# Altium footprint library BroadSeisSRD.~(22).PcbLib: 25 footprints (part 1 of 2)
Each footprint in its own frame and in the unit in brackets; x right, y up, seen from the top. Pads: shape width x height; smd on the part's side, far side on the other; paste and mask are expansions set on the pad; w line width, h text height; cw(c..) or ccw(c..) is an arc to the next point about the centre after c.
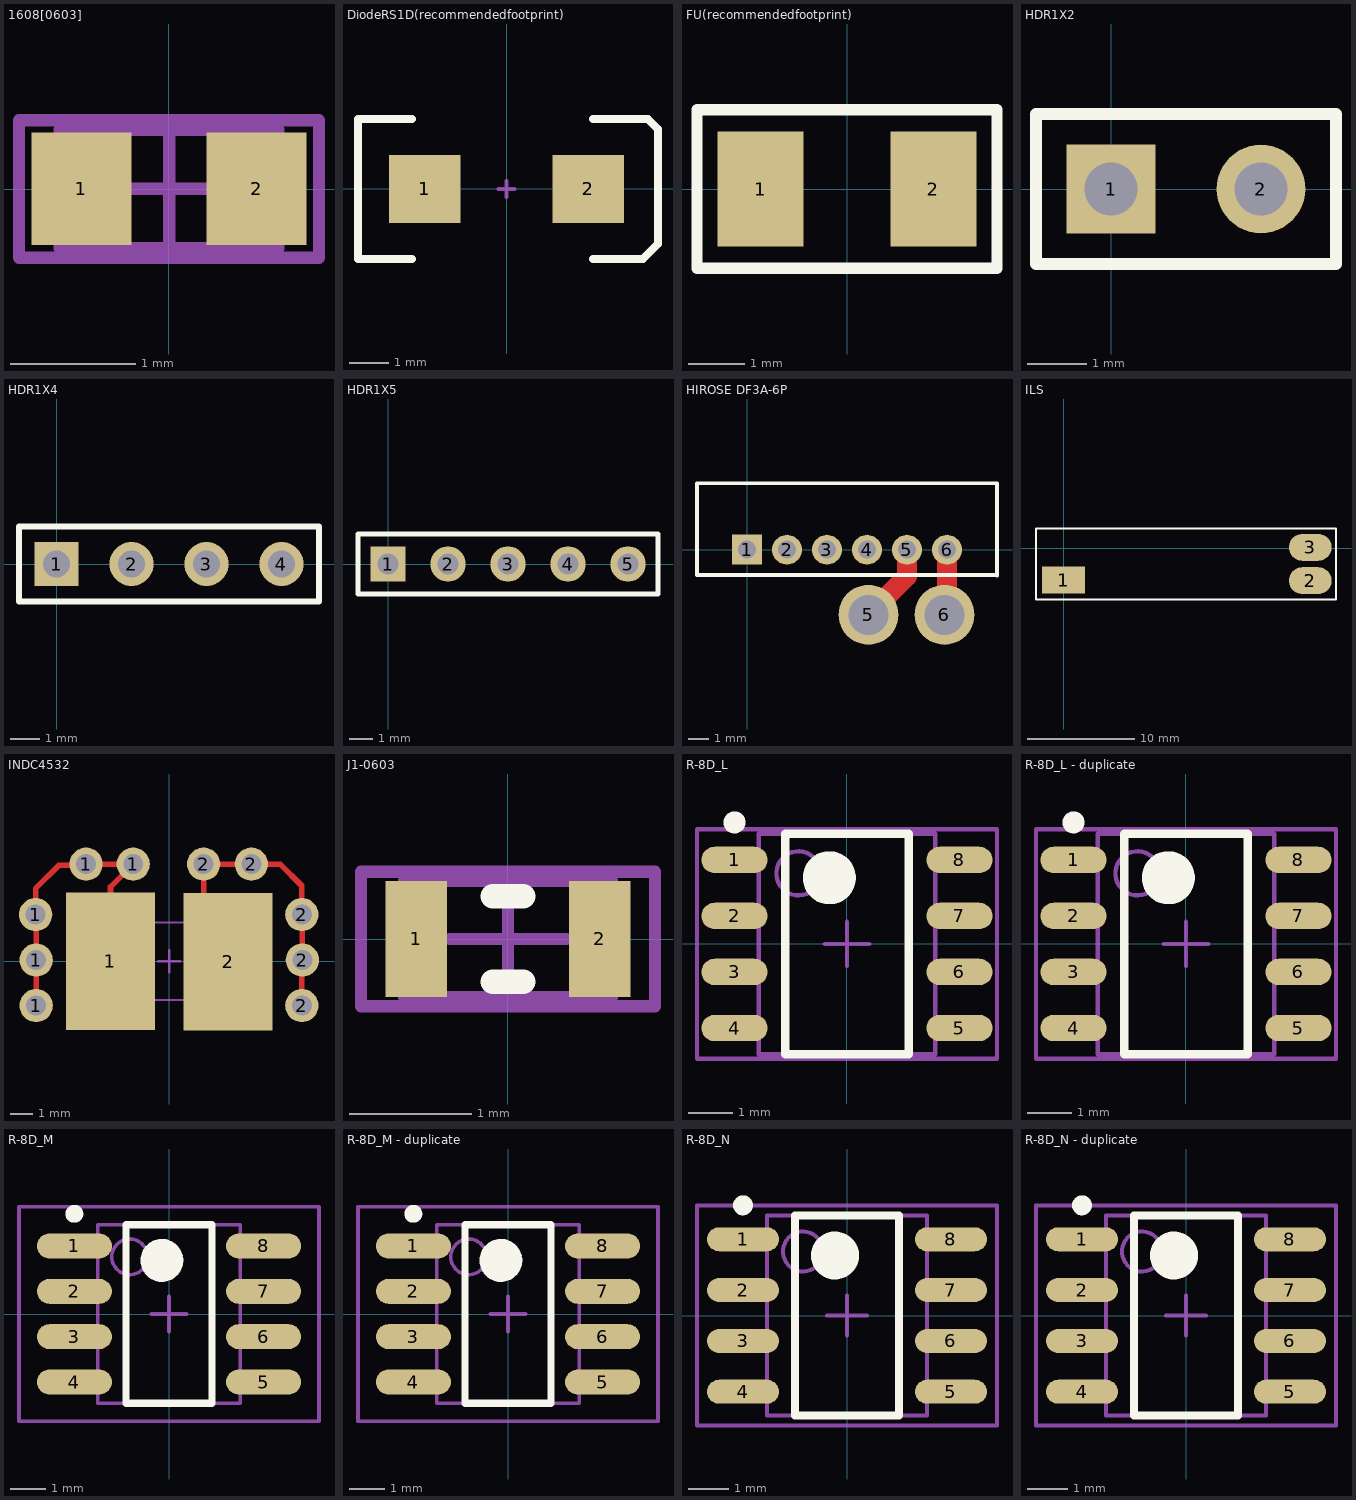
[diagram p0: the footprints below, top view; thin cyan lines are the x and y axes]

## 1608[0603] [mm] "Chip Capacitor, Body 1.6x0.8mm, IPC High Density"
height 1.3
pads (2):
  rect 0.8x0.9 smd: 1(-0.7,0) 2(0.7,0)
Mechanical 13:
  lines w0.1: -0.875,-0.475 0.875,-0.475 0.875,0.475 -0.875,0.475 -0.875,-0.475
Mechanical 15:
  lines w0.1: -0.475,0 0.475,0 ; 0,-0.475 0,0.475 ; -1.2,-0.55 1.2,-0.55 1.2,0.55 -1.2,0.55 -1.2,-0.55
3D body: height 1.3, standoff 0, extent -0.875,-0.475 0.875,0.475

## DiodeRS1D(recommendedfootprint) [mm] "DO-214-AB/SMC; 2 C-Bend Leads; Body 7.9 x 5.9 mm, inc. leads (LxW)"
height 2.65
pads (2):
  rect 1.8x1.7 smd: 1(-2.05,0) 2(2.05,0)
Top Overlay:
  lines w0.2: -2.375,-1.75 -3.725,-1.75 -3.725,1.75 -2.375,1.75 ; 2.175,-1.75 3.425,-1.75 3.8,-1.375 3.8,1.499 3.552,1.75 2.175,1.75
Mechanical 1:
  lines w0.1: -0.2,0 0.2,0 ; 0,-0.2 0,0.2

## FU(recommendedfootprint) [mm] "Thru-Hole; 2 Leads"
pads (2):
  rect 1.52x2.03 smd: 1(-1.525,0) 2(1.525,0)
Top Overlay:
  lines w0.2: -2.65,-1.4 2.65,-1.4 2.65,1.4 -2.65,1.4 -2.65,-1.4

## HDR1X2 [mm] "Connector; Header; 2 Position"
pads (2):
  rect 1.5x1.5 hole 0.9: 1(0,0)
  round 1.5 hole 0.9: 2(2.54,0)
Top Overlay:
  lines w0.2: -1.27,-1.27 3.81,-1.27 3.81,1.27 -1.27,1.27 -1.27,-1.27

## HDR1X4 [mm] "Connector; Header; 4 Position"
pads (4):
  rect 1.5x1.5 hole 0.9: 1(0,0)
  round 1.5 hole 0.9: 2(2.54,0) 3(5.08,0) 4(7.62,0)
Top Overlay:
  lines w0.2: -1.27,-1.27 -1.27,1.27 8.89,1.27 8.89,-1.27 -1.27,-1.27

## HDR1X5 [mm] "Connector; Header; 5 Position"
pads (5):
  rect 1.5x1.5 hole 0.9: 1(0,0)
  round 1.5 hole 0.9: 2(2.54,0) 3(5.08,0) 4(7.62,0) 5(10.16,0)
Top Overlay:
  lines w0.2: -1.27,-1.27 -1.27,1.27 11.43,1.27 11.43,-1.27 -1.27,-1.27

## HIROSE DF3A-6P [mm] "Connector; Header; 6 Position"
pads (8):
  rect 1.5x1.5 hole 0.9: 1(0,0)
  round 1.5 hole 0.9: 2(2,0) 3(4,0) 4(6,0) 5(8,0) 6(10,0)
  round 3 hole 2: 5(6.075,-3.25) 6(9.875,-3.25)
Top Layer:
  lines w0.254: 9.875,-3.25 10,-2.75
  lines w1: 6.075,-3.25 8,-1.325 8,0 ; 10,-2.75 10,0
Top Overlay:
  lines w0.2: 12.5,-1.29 12.5,3.325 -2.5,3.325 -2.5,-1.27 12.5,-1.27

## ILS [mm]
pads (3):
  rect 4x2.5 smd: 1(0,-2.95)
  oval 4x2.5 smd: 2(23,-3) 3(23,0.1)
Top Overlay:
  lines w0.2: -2.575,-4.775 25.4,-4.775 25.4,1.85 -2.575,1.85 -2.575,-4.775

## INDC4532 [mm] "Chip Inductor, Body 4.5x3.2mm, IPC High Density"
height 0.55
pads (12):
  round 1.5 hole 0.9: 1(-6.025,2.1) 1(-6,-2) 1(-6,0.05) 1(-3.75,4.375) 1(-1.625,4.375) 2(1.55,4.375) 2(3.7,4.375) 2(5.975,-2) 2(5.975,2.1) 2(6,0.05)
  rect 4x6.2 smd: 1(-2.65,0) 2(2.65,-0.025)
Top Layer:
  lines w0.254: -6,-2 -6,0.05 ; -5.975,0.075 -6,0.05 ; -5.825,2.075 -6.025,2.1 ; -3.725,4.15 -3.75,4.375 ; -1.625,1.025 -2.65,0 -2.65,3.35 -1.625,4.375 -3.75,4.375 ; 2.65,1.2 2.65,-0.025 1.55,1.075 1.55,4.375 3.7,4.375 ; 3.725,4.2 3.7,4.375 ; 3.75,4.425 3.7,4.375 ; 5.95,-1.975 5.975,-2 5.975,0.025 ; -6.025,2.1 -6,2.075 -6,0.05 ; -6.025,2.1 -6.025,3.275 -4.975,4.325 -3.8,4.325 -3.75,4.375 ; 3.7,4.375 5,4.375 5.975,3.4 5.975,2.1 ; 5.975,0.025 6,0.05 ; 5.975,0.025 6,0.05 ; 5.975,2.1 6,2.075 ; 5.975,2.1 6,2.075 ; 6,0.05 6,2.075
Mechanical 13:
  lines w0.1: -2.4,-1.7 -2.4,1.7 ; 2.4,-1.7 2.4,1.7
Mechanical 15:
  lines w0.1: -0.5,0 0.5,0 ; 0,-0.5 0,0.5 ; -2.7,-1.75 2.7,-1.75 2.7,1.75 -2.7,1.75 -2.7,-1.75

## J1-0603 [mm] "Chip Resistor, Body 1.6x0.8mm, IPC High Density"
height 0.9
pads (2):
  rect 0.5x0.95 smd: 1(-0.75,0) 2(0.75,0)
Top Overlay:
  lines w0.2: -0.125,-0.35 0.125,-0.35 ; -0.125,0.35 0.125,0.35
Mechanical 13:
  lines w0.1: -0.85,-0.475 0.85,-0.475 0.85,0.475 -0.85,0.475 -0.85,-0.475
Mechanical 15:
  lines w0.1: -0.475,0 0.475,0 ; 0,-0.475 0,0.475 ; -1.2,-0.55 1.2,-0.55 1.2,0.55 -1.2,0.55 -1.2,-0.55
3D body: height 0.9, standoff 0, extent -0.85,-0.475 0.85,0.475

## R-8D_L [mm] "SOIC, 8-Leads, Body 4.9x3.9mm, Pitch 1.27mm, IPC High Density"
height 2.59
pads (8):
  oval 1.5x0.6 smd: 1(-2.55,1.905) 2(-2.55,0.635) 3(-2.55,-0.635) 4(-2.55,-1.905) 5(2.55,-1.905) 6(2.55,-0.635) 7(2.55,0.635) 8(2.55,1.905)
Top Overlay:
  circle w0.6: c-0.4,1.5 r0.3
  circle w0.25: c-2.55,2.755 r0.125
  lines w0.2: -1.4,-2.5 1.4,-2.5 1.4,2.5 -1.4,2.5 -1.4,-2.5
Mechanical 13:
  circle w0.1: c-1.1,1.6 r0.5
  lines w0.1: -2,-2.5 2,-2.5 2,2.5 -2,2.5 -2,-2.5
Mechanical 15:
  lines w0.1: -0.5,0 0.5,0 ; 0,-0.5 0,0.5 ; -3.4,-2.6 3.4,-2.6 3.4,2.6 -3.4,2.6 -3.4,-2.6
3D body: height 2.59, standoff 0, extent -2,-2.5 2,2.5

## R-8D_L - duplicate [mm] "SOIC, 8-Leads, Body 4.9x3.9mm, Pitch 1.27mm, IPC High Density"
height 2.59
pads (8):
  oval 1.5x0.6 smd: 1(-2.55,1.905) 2(-2.55,0.635) 3(-2.55,-0.635) 4(-2.55,-1.905) 5(2.55,-1.905) 6(2.55,-0.635) 7(2.55,0.635) 8(2.55,1.905)
Top Overlay:
  circle w0.6: c-0.4,1.5 r0.3
  circle w0.25: c-2.55,2.755 r0.125
  lines w0.2: -1.4,-2.5 1.4,-2.5 1.4,2.5 -1.4,2.5 -1.4,-2.5
Mechanical 13:
  circle w0.1: c-1.1,1.6 r0.5
  lines w0.1: -2,-2.5 2,-2.5 2,2.5 -2,2.5 -2,-2.5
Mechanical 15:
  lines w0.1: -0.5,0 0.5,0 ; 0,-0.5 0,0.5 ; -3.4,-2.6 3.4,-2.6 3.4,2.6 -3.4,2.6 -3.4,-2.6
3D body: height 2.59, standoff 0, extent -2,-2.5 2,2.5

## R-8D_M [mm] "SOIC, 8-Leads, Body 4.9x3.9mm, Pitch 1.27mm, IPC Low Density"
height 2.59
pads (8):
  oval 2.1x0.7 smd: 1(-2.65,1.905) 2(-2.65,0.635) 3(-2.65,-0.635) 4(-2.65,-1.905) 5(2.65,-1.905) 6(2.65,-0.635) 7(2.65,0.635) 8(2.65,1.905)
Top Overlay:
  circle w0.25: c-2.65,2.805 r0.125
  circle w0.6: c-0.2,1.5 r0.3
  lines w0.2: -1.2,-2.5 -1.2,2.5 1.2,2.5 1.2,-2.5 -1.2,-2.5
Mechanical 13:
  circle w0.1: c-1.1,1.6 r0.5
  lines w0.1: -2,-2.5 -2,2.5 2,2.5 2,-2.5 -2,-2.5
Mechanical 15:
  lines w0.1: -0.5,0 0.5,0 ; 0,-0.5 0,0.5 ; -4.2,-3 -4.2,3 4.2,3 4.2,-3 -4.2,-3
3D body: height 2.59, standoff 0, extent -2,-2.5 2,2.5

## R-8D_M - duplicate [mm] "SOIC, 8-Leads, Body 4.9x3.9mm, Pitch 1.27mm, IPC Low Density"
height 2.59
pads (8):
  oval 2.1x0.7 smd: 1(-2.65,1.905) 2(-2.65,0.635) 3(-2.65,-0.635) 4(-2.65,-1.905) 5(2.65,-1.905) 6(2.65,-0.635) 7(2.65,0.635) 8(2.65,1.905)
Top Overlay:
  circle w0.25: c-2.65,2.805 r0.125
  circle w0.6: c-0.2,1.5 r0.3
  lines w0.2: -1.2,-2.5 -1.2,2.5 1.2,2.5 1.2,-2.5 -1.2,-2.5
Mechanical 13:
  circle w0.1: c-1.1,1.6 r0.5
  lines w0.1: -2,-2.5 -2,2.5 2,2.5 2,-2.5 -2,-2.5
Mechanical 15:
  lines w0.1: -0.5,0 0.5,0 ; 0,-0.5 0,0.5 ; -4.2,-3 -4.2,3 4.2,3 4.2,-3 -4.2,-3
3D body: height 2.59, standoff 0, extent -2,-2.5 2,2.5

## R-8D_N [mm] "SOIC, 8-Leads, Body 4.9x3.9mm, Pitch 1.27mm, IPC Medium Density"
height 2.59
pads (8):
  oval 1.8x0.6 smd: 1(-2.6,1.905) 2(-2.6,0.635) 3(-2.6,-0.635) 4(-2.6,-1.905) 5(2.6,-1.905) 6(2.6,-0.635) 7(2.6,0.635) 8(2.6,1.905)
Top Overlay:
  circle w0.6: c-0.3,1.5 r0.3
  circle w0.25: c-2.6,2.755 r0.125
  lines w0.2: -1.3,-2.5 1.3,-2.5 1.3,2.5 -1.3,2.5 -1.3,-2.5
Mechanical 13:
  circle w0.1: c-1.1,1.6 r0.5
  lines w0.1: -2,-2.5 2,-2.5 2,2.5 -2,2.5 -2,-2.5
Mechanical 15:
  lines w0.1: -0.5,0 0.5,0 ; 0,-0.5 0,0.5 ; -3.75,-2.75 3.75,-2.75 3.75,2.75 -3.75,2.75 -3.75,-2.75
3D body: height 2.59, standoff 0, extent -2,-2.5 2,2.5

## R-8D_N - duplicate [mm] "SOIC, 8-Leads, Body 4.9x3.9mm, Pitch 1.27mm, IPC Medium Density"
height 2.59
pads (8):
  oval 1.8x0.6 smd: 1(-2.6,1.905) 2(-2.6,0.635) 3(-2.6,-0.635) 4(-2.6,-1.905) 5(2.6,-1.905) 6(2.6,-0.635) 7(2.6,0.635) 8(2.6,1.905)
Top Overlay:
  circle w0.6: c-0.3,1.5 r0.3
  circle w0.25: c-2.6,2.755 r0.125
  lines w0.2: -1.3,-2.5 1.3,-2.5 1.3,2.5 -1.3,2.5 -1.3,-2.5
Mechanical 13:
  circle w0.1: c-1.1,1.6 r0.5
  lines w0.1: -2,-2.5 2,-2.5 2,2.5 -2,2.5 -2,-2.5
Mechanical 15:
  lines w0.1: -0.5,0 0.5,0 ; 0,-0.5 0,0.5 ; -3.75,-2.75 3.75,-2.75 3.75,2.75 -3.75,2.75 -3.75,-2.75
3D body: height 2.59, standoff 0, extent -2,-2.5 2,2.5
